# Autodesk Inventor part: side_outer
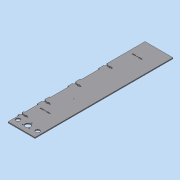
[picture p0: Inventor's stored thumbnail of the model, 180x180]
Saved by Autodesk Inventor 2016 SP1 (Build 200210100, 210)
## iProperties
Created: 2016-06
Part Number: side_outer
Material: Generic
Document SubType Name: Modeling
Designer: Mohamed A.
Density: 1 g/cm^3
Appearance: Default
d0: 1.000 ul
d0_1: 85.000 mm
d1: 320.000 mm
d2: 3.000 mm
d3: 0.00 deg
Author: Mohamed A.
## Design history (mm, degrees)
derived "side.ipt" dims count "d0" = 1
sketch "Sketch2"
  geometry: 1 further point
sketch "Sketch3"
  geometry: L1 (3, 273.4)-(0, 273.4) reference; L2 (85, 320)-(3, 320) reference; L3 (3, 273.4)-(3, 320) reference; L4 (3, 320)-(0, 320); L5 (0, 320)-(0, 278.4); L6 (0, 278.4)-(3, 278.4); L7 (3, 221.8)-(0, 221.8); L8 (0, 221.8)-(0, 185.2); L9 (0, 185.2)-(3, 185.2); L10 (0, 226.8)-(3, 226.8) reference; L11 (3, 180.2)-(0, 180.2) reference; L12 (0, 128.6)-(3, 128.6); L13 (3, 128.6)-(3, 92); L14 (3, 92)-(0, 92); L15 (0, 92)-(0, 128.6); L16 (0, 133.6)-(3, 133.6) reference; L17 (3, 221.8)-(3, 185.2); L18 (3, 226.8)-(3, 180.2) reference; L19 (3, 56)-(3, 28) reference; L20 (3, 51)-(0, 51); L21 (0, 51)-(0, 33); L22 (0, 33)-(3, 33); L23 (3, 33)-(3, 51); L24 (0, 56)-(3, 56) reference; L25 (3, 28)-(0, 28) reference; L26 (3, 87)-(0, 87) reference; 1 further point
  constraints: 30 end point, 6 perpendicular, 4 horizontal, 4 parallel, 2 collinear, 2 point on line
  dimensions: "d4" = 5 distance between parallel lines of L1 L6; "d5" = 5 distance between parallel lines of L10 L7; "d6" = 5 distance between parallel lines of L11 L9; "d7" = 5 distance between parallel lines of L16 L12; "d58" = 5 distance between parallel lines of L24 L20; "d59" = 5 distance between parallel lines of L25 L22; "d72" = 5 distance between parallel lines of L26 L14
extrude "Extrusion1" join sketch "Sketch3" distance "d9" = 3; taper "d10" = 0 deg
sketch "Sketch4"
  geometry: L1 (0, 273.4)-(3, 273.4) reference; L2 (0, 273.4)-(3, 273.4); L3 (3, 273.4)-(3, 226.8); L4 (3, 226.8)-(0, 226.8); L5 (0, 226.8)-(0, 273.4); L6 (0, 180.2)-(3, 180.2) reference; L7 (0, 180.2)-(3, 180.2); L8 (3, 180.2)-(3, 133.424); L9 (3, 133.424)-(0, 133.424); L10 (0, 133.424)-(0, 180.2); L11 (0, 248.55)-(0, 251.65); L12 (0, 28)-(0, 56) reference; L13 (0, 87)-(3, 87); L14 (3, 87)-(3, 56); L15 (3, 56)-(0, 56); L16 (0, 56)-(0, 87); L17 (0, 28)-(0, 0) reference; L18 (0, 28)-(3, 28); L19 (3, 28)-(3, 0); L20 (3, 0)-(0, 0); L21 (0, 0)-(0, 28); 1 further point
  constraints: 34 end point, 8 parallel, 4 horizontal, 4 perpendicular, 3 point on line
extrude "Extrusion2" cut sketch "Sketch4" distance "d11" = 3; taper "d12" = 0 deg
sketch "Sketch5"
  geometry: L1 (0, 300.75)-(21, 300.75); L2 (21, 300.75)-(21, 297.65); L3 (21, 297.65)-(0, 297.65); L4 (0, 297.65)-(0, 300.75); L5 (13, 302.2)-(16, 302.2); L6 (16, 302.2)-(16, 296.2); L7 (16, 296.2)-(13, 296.2); L8 (13, 296.2)-(13, 302.2); L9 (25.696, 299.2)-(-8.259, 299.2); L10 (0, 278.4)-(0, 320) reference; L11 (3, 278.4)-(0, 278.4) reference; L12 (85, 320)-(0, 320) reference; L13 (0, 303.7)-(3, 303.7); L14 (3, 303.7)-(3, 294.7); L15 (3, 294.7)-(0, 294.7); L16 (0, 294.7)-(0, 303.7); L17 (3, 221.8)-(0, 221.8) reference; L18 (21, 201.95)-(0, 201.95); L19 (0, 205.05)-(21, 205.05); L20 (21, 205.05)-(21, 201.95); L21 (16, 200.5)-(13, 200.5); L22 (13, 200.5)-(13, 206.5); L23 (0, 208)-(3, 208); L24 (3, 208)-(3, 199); L25 (16, 206.5)-(16, 200.5); L26 (13, 206.5)-(16, 206.5); L27 (3, 199)-(0, 199); L28 (25.696, 203.5)-(-8.259, 203.5); L29 (0, 199)-(0, 208); L30 (21, 108.75)-(0, 108.75); L31 (0, 111.85)-(21, 111.85); L32 (21, 111.85)-(21, 108.75); L33 (16, 107.3)-(13, 107.3); L34 (13, 107.3)-(13, 113.3); L35 (0, 114.8)-(3, 114.8); L36 (3, 114.8)-(3, 105.8); L37 (16, 113.3)-(16, 107.3); L38 (13, 113.3)-(16, 113.3); L39 (3, 105.8)-(0, 105.8); L40 (25.696, 110.3)-(-8.259, 110.3); L41 (0, 105.8)-(0, 114.8); L42 (0, 185.2)-(3, 185.2) reference; L43 (3, 92)-(0, 92) reference; L44 (0, 128.6)-(3, 128.6) reference; L45 (0, 205.05)-(0, 201.95); L46 (0, 221.8)-(0, 185.2) reference; L47 (0, 111.85)-(0, 108.75); L48 (0, 92)-(0, 128.6) reference; L49 (0, 43.55)-(21, 43.55); L50 (0, 38.25)-(0, 45.75); L51 (0, 43.55)-(0, 40.45); L52 (21, 40.45)-(0, 40.45); L53 (3, 38.25)-(0, 38.25); L54 (0, 45.75)-(3, 45.75); L55 (3, 45.75)-(3, 38.25); L56 (13, 39)-(13, 45); L57 (13, 45)-(16, 45); L58 (16, 39)-(13, 39); L59 (16, 45)-(16, 39); L60 (21, 43.55)-(21, 40.45); L61 (25.696, 42)-(-8.259, 42); L62 (0, 33)-(3, 33) reference; L63 (3, 51)-(0, 51) reference; 1 further point
  constraints: 104 end point, 21 parallel, 16 horizontal, 12 perpendicular, 3 collinear, 1 point on line, 12 other
  dimensions: "d27" = 21 distance of L2.end L3.end; "d28" = 3.1 distance of L1.end L2.end; "d29" = 3 distance of L6.end L7.end; "d30" = 6 distance of L5.end L6.end; "d31" = 41.6 distance between parallel lines of L11 L12 (derived); "d32" = 20.8 distance between parallel lines of L9 L12 (= 0.5 x d31); "d33" = 5 distance between parallel lines of L6 L2; "d34" = 9 distance between parallel lines of L15 L13; "d35" = 3 distance between parallel lines of L16 L14; "d36" = 56.6 distance between parallel lines of L17 L11 (derived); "d37" = 21 distance of L18.start L18.end; "d38" = 3.1 distance of L19.end L18.start; "d39" = 3 distance of L21.start L21.end; "d40" = 6 distance of L25.start L21.start; "d41" = 5 distance between parallel lines of L25 L20; "d42" = 9 distance between parallel lines of L27 L23; "d43" = 3 distance between parallel lines of L29 L24; "d44" = 21 distance of L30.start L30.end; "d45" = 3.1 distance of L31.end L30.start; "d46" = 3 distance of L33.start L33.end; "d47" = 6 distance of L37.start L33.start; "d48" = 5 distance between parallel lines of L37 L32; "d49" = 9 distance between parallel lines of L39 L35; "d50" = 3 distance between parallel lines of L41 L36; "d52" = 36.6 distance between parallel lines of L17 L42 (derived); "d53" = 18.3 distance between parallel lines of L28 L17 (= 0.5 x d52); "d54" = 36.6 distance between parallel lines of L43 L44 (derived); "d55" = 18.3 distance between parallel lines of L44 L40 (= 0.5 x d54); "d60" = 21 distance of L52.start L51.end; "d61" = 3.1 distance of L49.end L52.start; "d62" = 3 distance of L58.start L56.start; "d63" = 6 distance of L57.end L58.start; "d64" = 5 distance between parallel lines of L59 L60; "d65" = 7.5 distance between parallel lines of L53 L54; "d66" = 3 distance between parallel lines of L50 L55; "d67" = 18 distance between parallel lines of L62 L63 (derived); "d68" = 9 distance between parallel lines of L61 L63 (= 0.5 x d67)
extrude "Extrusion3" cut sketch "Sketch5" distance "d56" = 3; taper "d57" = 0 deg
sketch "Sketch7"
  geometry: L1 (0, 0)-(-85, 0) reference; L2 (0, 3)-(0, 0) reference; L3 (-85, 3)-(0, 3) reference; L4 (-85, 0)-(-85, 3) reference; 1 further point
extrude "Extrusion5" join sketch "Sketch7" distance "d73" = 100; taper "d74" = 0 deg
sketch "Sketch8"
  geometry: L1 (64, 43.55)-(69, 43.55) reference; L2 (69, 43.55)-(69, 45) reference; L3 (69, 45)-(72, 45) reference; L4 (72, 45)-(72, 43.55) reference; L5 (72, 43.55)-(82, 43.55) reference; L6 (82, 43.55)-(82, 45.75) reference; L7 (82, 45.75)-(85, 45.75) reference; L8 (85, 45.75)-(85, 51) reference; L9 (85, 51)-(82, 51) reference; L10 (82, 51)-(82, 92) reference; L11 (82, 92)-(85, 92) reference; L12 (85, 92)-(85, 105.8) reference; L13 (85, 105.8)-(82, 105.8) reference; L14 (82, 105.8)-(82, 108.75) reference; L15 (82, 108.75)-(72, 108.75) reference; L16 (72, 108.75)-(72, 107.3) reference; L17 (72, 107.3)-(69, 107.3) reference; L18 (69, 107.3)-(69, 108.75) reference; L19 (69, 108.75)-(64, 108.75) reference; L20 (64, 108.75)-(64, 111.85) reference; L21 (64, 111.85)-(69, 111.85) reference; L22 (69, 111.85)-(69, 113.3) reference; L23 (69, 113.3)-(72, 113.3) reference; L24 (72, 113.3)-(72, 111.85) reference; L25 (72, 111.85)-(82, 111.85) reference; L26 (82, 111.85)-(82, 114.8) reference; L27 (82, 114.8)-(85, 114.8) reference; L28 (85, 114.8)-(85, 128.6) reference; L29 (85, 128.6)-(82, 128.6) reference; L30 (82, 128.6)-(82, 185.2) reference; L31 (82, 185.2)-(85, 185.2) reference; L32 (85, 185.2)-(85, 199) reference; L33 (85, 199)-(82, 199) reference; L34 (82, 199)-(82, 201.95) reference; L35 (82, 201.95)-(72, 201.95) reference; L36 (72, 201.95)-(72, 200.5) reference; L37 (72, 200.5)-(69, 200.5) reference; L38 (69, 200.5)-(69, 201.95) reference; L39 (69, 201.95)-(64, 201.95) reference; L40 (64, 201.95)-(64, 205.05) reference; L41 (64, 205.05)-(69, 205.05) reference; L42 (69, 205.05)-(69, 206.5) reference; L43 (69, 206.5)-(72, 206.5) reference; L44 (72, 206.5)-(72, 205.05) reference; L45 (72, 205.05)-(82, 205.05) reference; L46 (82, 205.05)-(82, 208) reference; L47 (82, 208)-(85, 208) reference; L48 (85, 208)-(85, 221.8) reference; L49 (85, 221.8)-(82, 221.8) reference; L50 (82, 221.8)-(82, 278.4) reference; L51 (82, 278.4)-(85, 278.4) reference; L52 (85, 278.4)-(85, 294.7) reference; L53 (85, 294.7)-(82, 294.7) reference; L54 (82, 294.7)-(82, 297.65) reference; L55 (82, 297.65)-(72, 297.65) reference; L56 (72, 297.65)-(72, 296.2) reference; L57 (72, 296.2)-(69, 296.2) reference; L58 (69, 296.2)-(69, 297.65) reference; L59 (69, 297.65)-(64, 297.65) reference; L60 (64, 297.65)-(64, 300.75) reference; L61 (64, 300.75)-(69, 300.75) reference; L62 (69, 300.75)-(69, 302.2) reference; L63 (69, 302.2)-(72, 302.2) reference; L64 (72, 302.2)-(72, 300.75) reference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; C1 r 8.5 at (42.5, 21) reference; C2 r 6.3 at (72.2, 21) reference; C3 r 1.4 at (32.578, 15.272) reference; C4 r 1.4 at (54.505, 85.5) reference; C5 r 1.4 at (54.505, 288.5) reference; C6 r 1.4 at (42.5, 32.457) reference; C7 r 1.4 at (52.422, 15.272) reference; C8 r 6.3 at (12.8, 21) reference; 1 further point
extrude "Extrusion6" join sketch "Sketch8" distance "d75" = 3; taper "d76" = 0 deg
sketch "Sketch9"
  geometry: L1 (69.005, 367)-(69.005, 370) reference; L2 (69.005, 370)-(59.005, 370) reference; L3 (59.005, 370)-(59.005, 367) reference; L4 (59.005, 367)-(69.005, 367) reference; L5 (50.005, 367)-(50.005, 370) reference; L6 (50.005, 370)-(40.005, 370) reference; L7 (40.005, 370)-(40.005, 367) reference; L8 (40.005, 367)-(50.005, 367) reference; L9 (59.005, 84)-(69.005, 84) reference; L10 (69.005, 84)-(69.005, 87) reference; L11 (69.005, 87)-(59.005, 87) reference; L12 (59.005, 87)-(59.005, 84) reference; L13 (72, 39)-(72, 45) reference; L14 (72, 45)-(69, 45) reference; L15 (69, 45)-(69, 39) reference; L16 (69, 39)-(72, 39) reference; L17 (72, 296.2)-(72, 302.2) reference; L18 (72, 302.2)-(69, 302.2) reference; L19 (69, 302.2)-(69, 296.2) reference; L20 (69, 296.2)-(72, 296.2) reference; L21 (72, 200.5)-(72, 205.05) reference; L22 (72, 205.05)-(69, 205.05) reference; L23 (69, 205.05)-(69, 200.5) reference; L24 (69, 200.5)-(72, 200.5) reference; L25 (72, 107.3)-(72, 113.3) reference; L26 (72, 113.3)-(69, 113.3) reference; L27 (69, 113.3)-(69, 107.3) reference; L28 (69, 107.3)-(72, 107.3) reference; L29 (50.005, 87)-(40.005, 87) reference; L30 (40.005, 87)-(40.005, 84) reference; L31 (40.005, 84)-(50.005, 84) reference; L32 (50.005, 84)-(50.005, 87) reference; L33 (85, 133.6)-(82, 133.6) reference; L34 (82, 133.6)-(82, 87) reference; L35 (82, 87)-(85, 87) reference; L36 (85, 87)-(85, 56) reference; L37 (85, 56)-(82, 56) reference; L38 (82, 56)-(82, 28) reference; L39 (82, 28)-(85, 28) reference; L40 (85, 28)-(85, 0) reference; L41 (85, 0)-(0, 0) reference; L42 (0, 0)-(0, 420) reference; L43 (85, 420)-(0, 420) reference; L44 (85, 320)-(85, 420) reference; L45 (85, 320)-(82, 320) reference; L46 (82, 320)-(82, 273.4) reference; L47 (82, 273.4)-(85, 273.4) reference; L48 (85, 273.4)-(85, 226.8) reference; L49 (85, 226.8)-(82, 226.8) reference; L50 (82, 226.8)-(82, 180.2) reference; L51 (82, 180.2)-(85, 180.2) reference; L52 (85, 180.2)-(85, 133.6) reference; C1 r 1.4 at (54.505, 368.5) reference; C2 r 6.3 at (12.8, 21) reference; C3 r 1.4 at (52.422, 15.272) reference; C4 r 1.4 at (42.5, 32.457) reference; C5 r 1.4 at (54.505, 85.5) reference; C6 r 1.4 at (32.578, 15.272) reference; C7 r 6.3 at (72.2, 21) reference; C8 r 8.5 at (42.5, 21) reference; 1 further point
extrude "Extrusion7" cut sketch "Sketch9" distance "d77" = 3; taper "d78" = 0 deg
feature "Solid1::side.ipt" dims count "d0" = 1
tag "TaggingFeature1"
node "Projected Loop1"
node "Projected Loop2"
node "Reference3"
body "Solid1"
other parameters: "d0_1" = 85, "d1" = 320, "d2" = 3, "d3" = 0 deg
